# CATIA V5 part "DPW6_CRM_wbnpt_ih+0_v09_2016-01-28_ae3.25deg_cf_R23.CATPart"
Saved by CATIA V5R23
Part number: DPW6_CRM_wbnpt_ih+0_v09_2016-01-28_ae3
Bounding box of the stored display mesh (mm): x 2349.5 to 66711.883, y -0.001 to 29449.115, z -65.266 to 8715.76
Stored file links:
  C:\Users\mrg\work\AIAA_DPW\DPW6\DLR_meshes\all\3deg25\DPW6_CRM_wbnpt_ih+0_v09_2016-01-28_ae3.25deg_cf_R23.CATPart

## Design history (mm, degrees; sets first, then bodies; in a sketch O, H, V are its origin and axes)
MechanicalRefPlane1 "xy-plane"
MechanicalRefPlane2 "yz-plane"
MechanicalRefPlane3 "zx-plane"
Set1
  DatumSurface1 to DatumSurface3
Body1 (main body)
